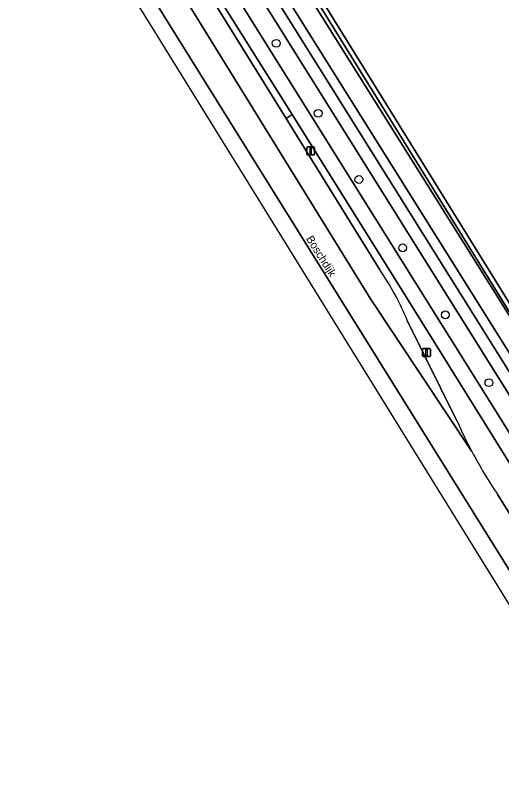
# Model space of a CAD drawing. Extents: x 159352 to 160617, y 385888 to 387323.
# Drawn here: x 159426.4 to 159487.1, y 386145.6 to 386241.7 of the extents above; entities that cross this region are included whole.
import ezdxf

# ---------------------------------------------------------------- set-up
doc = ezdxf.new("R2010")
doc.units = 0
for name, color, linetype in [('IMGEO_Berm_groen', 7, 'Continuous'), ('IMGEO_Boom', 7, 'Continuous'), ('IMGEO_Fietspad_gesloten', 7, 'Continuous'), ('IMGEO_Groenvoorziening', 7, 'Continuous'), ('IMGEO_Haag', 7, 'Continuous'), ('IMGEO_Lichtmast', 7, 'Continuous'), ('IMGEO_Openbare_ruimte_label', 7, 'Continuous'), ('IMGEO_Rijbaan_regionaal_gesloten', 7, 'Continuous'), ('IMGEO_Voetpad_open', 7, 'Continuous'), ('IMGEO_Waterloop', 7, 'Continuous')]:
    doc.layers.add(name, color=color, linetype=linetype)

msp = doc.modelspace()

# ---------------------------------------------------------------- linework, layer by layer
at = {"layer": 'IMGEO_Berm_groen'}
msp.add_lwpolyline([(159361.592, 386399.829), (159362.056, 386399.085), (159455.092, 386250), (159500, 386178.036), (159518.514, 386148.338), (159519.603, 386148.98), (159500, 386180.471), (159456.532, 386250), (159379.941, 386372.509), (159362.875, 386400.189), (159362.418, 386400.931), (159362.418, 386400.931)], close=True, dxfattribs=at)
for points in [[(159548.371, 386097.594), (159545.848, 386101.702), (159531.743, 386124.354), (159519.361, 386144.039), (159517.175, 386147.549), (159507.63, 386162.875), (159501.77, 386172.355), (159500, 386175.187), (159458.712, 386241.251), (159453.256, 386250), (159435.15, 386279.032), (159415.41, 386310.673), (159399.888, 386335.332), (159389.058, 386352.807), (159376.566, 386372.971), (159363.439, 386393.878), (159361.065, 386397.75), (159360.601, 386398.506), (159358.992, 386396.356)], [(159358.992, 386396.356), (159358.992, 386396.356), (159359.467, 386395.596), (159381.824, 386359.807), (159396.397, 386336.533), (159416.709, 386303.89), (159434.509, 386275.359), (159450.358, 386250), (159490.603, 386185.487), (159500, 386170.463), (159500.342, 386169.916), (159512.48, 386150.408), (159515.059, 386146.301), (159542.856, 386101.021), (159544.684, 386098.275), (159544.867, 386098)], [(159428.046, 386275.581), (159470.735, 386206.335), (159483.378, 386187.265)], [(159471.898, 386209.929), (159460.205, 386228.859), (159448.338, 386248.072)], [(159504.636, 386159.124), (159501.671, 386163.914), (159500, 386166.602), (159474.127, 386208.217), (159460.945, 386229.331), (159460.205, 386228.859), (159471.898, 386209.929)], [(159475.338, 386203.552), (159481.521, 386191.1)], [(159481.521, 386191.1), (159475.338, 386203.552)], [(159486.623, 386181.834), (159500, 386160.345), (159500.36, 386159.767), (159508.686, 386146.315), (159510.41, 386143.562), (159519.207, 386129.517), (159536.038, 386102.53), (159539.905, 386096.263), (159546.132, 386086.251), (159547.558, 386083.97), (159548.024, 386084.243)]]:
    msp.add_lwpolyline(points, dxfattribs=at)
for centre, radius, start, end in [((159446.099, 386191.896), 31.477, 21.73504, 34.95323), ((159446.099, 386191.896), 31.477, 21.73504, 34.95323), ((159537.132, 386215.661), 60.793, 203.82908, 207.8457), ((159537.132, 386215.661), 60.793, 203.82908, 207.8457), ((159536.601, 386215.381), 60.193, 207.84571, 213.87058)]:
    msp.add_arc(centre, radius, start, end, dxfattribs=at)
at = {"layer": 'IMGEO_Boom'}
for centre in [(159458.978, 386238.234), (159464.209, 386229.49), (159469.287, 386221.227), (159474.746, 386212.686), (159480.078, 386204.323), (159485.512, 386195.858)]:
    msp.add_circle(centre, 0.489, dxfattribs=at)
at = {"layer": 'IMGEO_Fietspad_gesloten'}
for points in [[(159542.856, 386101.021), (159515.059, 386146.301), (159512.48, 386150.408), (159500.342, 386169.916), (159500, 386170.463), (159490.603, 386185.487), (159450.358, 386250)], [(159448.583, 386249.132), (159460.945, 386229.331), (159474.127, 386208.217), (159500, 386166.602), (159501.671, 386163.914), (159504.636, 386159.124), (159513.312, 386145.273)]]:
    msp.add_lwpolyline(points, dxfattribs=at)
at = {"layer": 'IMGEO_Groenvoorziening'}
msp.add_lwpolyline([(159469.384, 386427.253), (159474.123, 386431.798), (159464.607, 386446.619), (159463.993, 386447.575), (159460.866, 386452.718), (159450.601, 386448.684), (159437.125, 386443.389), (159436.243, 386443.042), (159392.607, 386417.051), (159393.962, 386414.948), (159407.698, 386393.628), (159382.354, 386376.783), (159419.283, 386316.377), (159458.061, 386254.291), (159460.741, 386250), (159500, 386186.48), (159520.962, 386153.341), (159520.51, 386153.027), (159521.879, 386150.588), (159523.149, 386152.545), (159524.56, 386155.081), (159530.909, 386143.925)], dxfattribs=at)
for points in [[(159460.741, 386250), (159458.061, 386254.291), (159419.283, 386316.377), (159382.354, 386376.783), (159382.188, 386376.672), (159381.896, 386376.477), (159418.815, 386316.088), (159457.595, 386254), (159460.274, 386249.71), (159499.534, 386186.188), (159520.51, 386153.027), (159520.962, 386153.341), (159500, 386186.48)], [(159418.815, 386316.088), (159381.896, 386376.477), (159381.378, 386376.132), (159428.317, 386299.74), (159459.428, 386250), (159500, 386185.135), (159521.718, 386150.228), (159521.879, 386150.588), (159520.51, 386153.027), (159499.534, 386186.188), (159460.274, 386249.71), (159457.595, 386254)]]:
    msp.add_lwpolyline(points, close=True, dxfattribs=at)
at = {"layer": 'IMGEO_Haag'}
msp.add_lwpolyline([(159382.354, 386376.783), (159382.188, 386376.672), (159381.896, 386376.477), (159418.815, 386316.088), (159457.595, 386254), (159460.274, 386249.71), (159499.534, 386186.188), (159520.51, 386153.027), (159520.962, 386153.341), (159500, 386186.48), (159460.741, 386250), (159458.061, 386254.291), (159419.283, 386316.377)], close=True, dxfattribs=at)
at = {"layer": 'IMGEO_Lichtmast'}
for p, q in [((159462.773, 386224.388), (159462.773, 386225.188)), ((159462.773, 386225.188), (159462.773, 386224.388)), ((159462.873, 386225.288), (159463.663, 386225.288)), ((159463.663, 386225.288), (159462.873, 386225.288)), ((159463.763, 386225.188), (159463.763, 386224.388)), ((159463.763, 386224.388), (159463.763, 386225.188)), ((159463.663, 386224.288), (159462.873, 386224.288)), ((159462.873, 386224.288), (159463.663, 386224.288)), ((159477.22, 386199.217), (159477.22, 386200.017)), ((159477.22, 386200.017), (159477.22, 386199.217)), ((159477.32, 386200.117), (159478.11, 386200.117)), ((159478.11, 386200.117), (159477.32, 386200.117)), ((159478.21, 386200.017), (159478.21, 386199.217)), ((159478.21, 386199.217), (159478.21, 386200.017)), ((159478.11, 386199.117), (159477.32, 386199.117)), ((159477.32, 386199.117), (159478.11, 386199.117))]:
    msp.add_line(p, q, dxfattribs=at)
for points in [[(159463.193, 386225.163), (159463.343, 386225.163), (159463.343, 386224.413), (159463.193, 386224.413), (159463.193, 386225.163)], [(159477.64, 386199.992), (159477.79, 386199.992), (159477.79, 386199.242), (159477.64, 386199.242), (159477.64, 386199.992)]]:
    msp.add_lwpolyline(points, dxfattribs=at)
for centre, start, end in [((159462.873, 386225.188), 90, 180), ((159462.873, 386225.188), 90, 180), ((159463.663, 386225.188), 0, 90), ((159463.663, 386225.188), 360, 90), ((159462.873, 386224.388), 180, 270), ((159462.873, 386224.388), 180, 270), ((159463.663, 386224.388), 270, 0), ((159463.663, 386224.388), 270, 0), ((159477.32, 386200.017), 90, 180), ((159477.32, 386200.017), 90, 180), ((159478.11, 386200.017), 0, 90), ((159478.11, 386200.017), 360, 90), ((159477.32, 386199.217), 180, 270), ((159477.32, 386199.217), 180, 270), ((159478.11, 386199.217), 270, 0), ((159478.11, 386199.217), 270, 0)]:
    msp.add_arc(centre, 0.1, start, end, dxfattribs=at)
at = {"layer": 'IMGEO_Rijbaan_regionaal_gesloten'}
msp.add_lwpolyline([(159353.179, 386388.594), (159352.236, 386387.335), (159429.513, 386262.812), (159505.134, 386140.452), (159507.222, 386141.683), (159422.725, 386277.362), (159353.678, 386387.795), (159353.179, 386388.594)], close=True, dxfattribs=at)
for points in [[(159353.179, 386388.594), (159353.179, 386388.594), (159353.678, 386387.795), (159422.725, 386277.362), (159507.222, 386141.683), (159510.41, 386143.562), (159508.686, 386146.315), (159500.36, 386159.767), (159500, 386160.345), (159486.623, 386181.834)], [(159483.378, 386187.265), (159470.735, 386206.335), (159428.046, 386275.581)]]:
    msp.add_lwpolyline(points, dxfattribs=at)
msp.add_arc((159536.601, 386215.381), 60.193, 207.84571, 213.87058, dxfattribs=at)
at = {"layer": 'IMGEO_Voetpad_open'}
msp.add_lwpolyline([(159548.288, 386100.577), (159518.514, 386148.338), (159500, 386178.036), (159455.092, 386250), (159362.056, 386399.085), (159361.592, 386399.829), (159360.601, 386398.506), (159361.065, 386397.75), (159363.439, 386393.878), (159376.566, 386372.971), (159389.058, 386352.807), (159399.888, 386335.332), (159415.41, 386310.673), (159435.15, 386279.032), (159453.256, 386250), (159458.712, 386241.251), (159500, 386175.187), (159501.77, 386172.355), (159507.63, 386162.875), (159517.175, 386147.549), (159519.361, 386144.039)], dxfattribs=at)
msp.add_lwpolyline([(159448.583, 386249.132), (159447.92, 386248.737), (159448.338, 386248.072), (159460.205, 386228.859), (159460.945, 386229.331)], close=True, dxfattribs=at)
at = {"layer": 'IMGEO_Waterloop'}
msp.add_lwpolyline([(159364.462, 386403.661), (159362.418, 386400.931), (159362.418, 386400.931), (159362.875, 386400.189), (159379.941, 386372.509), (159456.532, 386250), (159500, 386180.471), (159519.603, 386148.98), (159521.718, 386150.228), (159500, 386185.135), (159459.428, 386250), (159428.317, 386299.74), (159381.378, 386376.132), (159364.91, 386402.932)], close=True, dxfattribs=at)

# ---------------------------------------------------------------- texts
at = {"layer": 'IMGEO_Openbare_ruimte_label'}
msp.add_text('Boschdijk', height=1, rotation=302.00538, dxfattribs=at).set_placement((159462.652, 386213.828))

doc.saveas('drawing.dxf')
